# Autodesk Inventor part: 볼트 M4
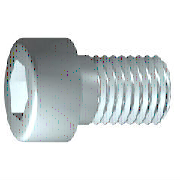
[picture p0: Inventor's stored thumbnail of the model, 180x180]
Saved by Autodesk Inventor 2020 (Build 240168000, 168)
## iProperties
Created: 2009-02
Part Number: 볼트 M4
Material: 강철, 연강
Description: 6각머리 태핑 나사
Document SubType Name: Modeling
Standard: KS B 1003
Standards Organization: KS
Language: ko-KR
Size Designation: M 4 x 12
Categories: <MemberInstance><Categories><Category DisplayName="조임쇠" InternalName="e4da775c-781d-43d5-af7c-5136215cf5a6" Mnemonic="FSTN"><Category DisplayName="볼트" InternalN
Density: 1 g/cm^3
Appearance: 차가운 흰색
IsCustomPart: 0
Author: pww
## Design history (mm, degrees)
sketch "스케치1"
  geometry: L1 (-1, 0)-(12, 0); L2 (12, 0)-(12, 2); L3 (12, 2)-(1.75, 2); L4 (1.75, 2)-(1.32, 2); L5 (1.32, 2)-(0, 2); L6 (0, 2)-(0, 3.5); L7 (0, 3.5)-(-4, 3.5); L8 (-4, 3.5)-(-4, 1.732); L9 (-4, 1.732)-(-2, 1.732); L10 (-2, 1.732)-(-1, 0); L11 (-7.2, 0)-(15.2, 0) reference; L12 (0, -0.7)-(0, 4.2) reference; L13 (1.75, 2)-(0, 2)
  constraints: 22 end point, 6 parallel, 2 collinear, 2 perpendicular, 1 horizontal, 1 point on line
  dimensions: "d1" = 10.25 distance from line of L3.end L2 (= GEL); "d2" = 0.42952 distance of L4.end L3.end (computed from GAL); "d3" = 4 distance between parallel lines of L8 L6 (= KOH); "d4" = 2 distance of L8.end L9.end (= INTI); "d5" = 60 deg angle of L10 L1; "d6" = 4 diameter of L3 L1 (= GD); "d7" = 4 diameter of L5 L1 (= BDM); "d8" = 3.4641 diameter of L9 L1 (= 1.1547 x SW); "d9" = 7 diameter of L7 L1 (= KOD); "d26" = 12 distance between parallel lines of L12 L2 (= NLG)
revolve "본체" sketch "스케치1" stored, may be unused: angle "d10" = 90 deg
sketch "스케치2"
  geometry: L1 (0, -4.9)-(0, 4.9) reference; L2 (-4.9, 0)-(4.9, 0) reference; L3 (1.732, 0)-(0.866, -1.5); L4 (0.866, -1.5)-(-0.866, -1.5); L5 (-0.866, -1.5)-(-1.732, 0); L6 (-1.732, 0)-(-0.866, 1.5); L7 (-0.866, 1.5)-(0.866, 1.5); L8 (0.866, 1.5)-(1.732, 0); 2 further points
  constraints: 12 end point, 1 coincident, 1 horizontal alignment, 1 point on line, 12 other
extrude "슬롯" join sketch "스케치2" stored distance "d11" = 10; taper "d12" = 0 deg
workplane "Work Plane1"
fillet "Fillet2" dims "d30" = 0.1 (= R)
body "Solid1"
fillet "모깎기1" dims "d17" = 0.4 (= RR)
feature "스레드" dims "d13" = 10.25 (= GEL), "d14" = 0
chamfer "모따기1" distance "d15" = 0.42941 (= -0.5 x SPD + 0.5 x GD); stored, may be unused: second distance "d16" = 0.42941 (= GUL), angle "d27" = 45 deg
other parameters: "GD" = 4 (= NND) [user parameter; used in 2 equation terms], "NLG" = 12 [user parameter; used in 1 equation term], "GEL" = 10.25 [user parameter; used in 2 equation terms], "KOD" = 7 [user parameter; used in 1 equation term], "KOH" = 4 [user parameter; used in 1 equation term], "INTI" = 2 [user parameter; used in 1 equation term], "GAL" = 0.42941 (= 0.61345 x PTC) [user parameter; used in 1 equation term], "GUL" = 0.42941 (= 0.61345 x PTC) [user parameter; used in 1 equation term], "BDM" = 4 (= NND) [user parameter; used in 1 equation term], "SW" = 3 [user parameter; used in 2 equation terms], "RR" = 0.4 [user parameter; used in 1 equation term], "SPD" = 3.14117 (= NND - 1.2269 x PTC) [user parameter; used in 1 equation term], "d19" = 0, "d28" = 0, "d29" = 0, "R" = 0.1 [user parameter; used in 1 equation term], "PHH" = 0.2 [user parameter], "GD1" = 3.14117 (= THREADDIA - 1.2269 x PTC) [user parameter], "THREADDIA" = 4 [user parameter; used in 1 equation term], "FAWI" = 45 deg [user parameter], "TPU" = 14.28571 (computed from PTC) [user parameter], "PTC" = 0.7 [user parameter; used in 5 equation terms], "NND" = 4 [user parameter; used in 3 equation terms], "TOA" = 30 deg [user parameter], "E0" = 3.465 (= 1.155 x SW) [user parameter]
